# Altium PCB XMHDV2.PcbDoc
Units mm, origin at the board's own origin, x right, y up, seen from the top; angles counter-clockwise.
Board outline 47.29 x 47.29 mm, 2 copper layers (Top Layer, Bottom Layer); 11 components, 11 nets, 140 pads, 0 vias.
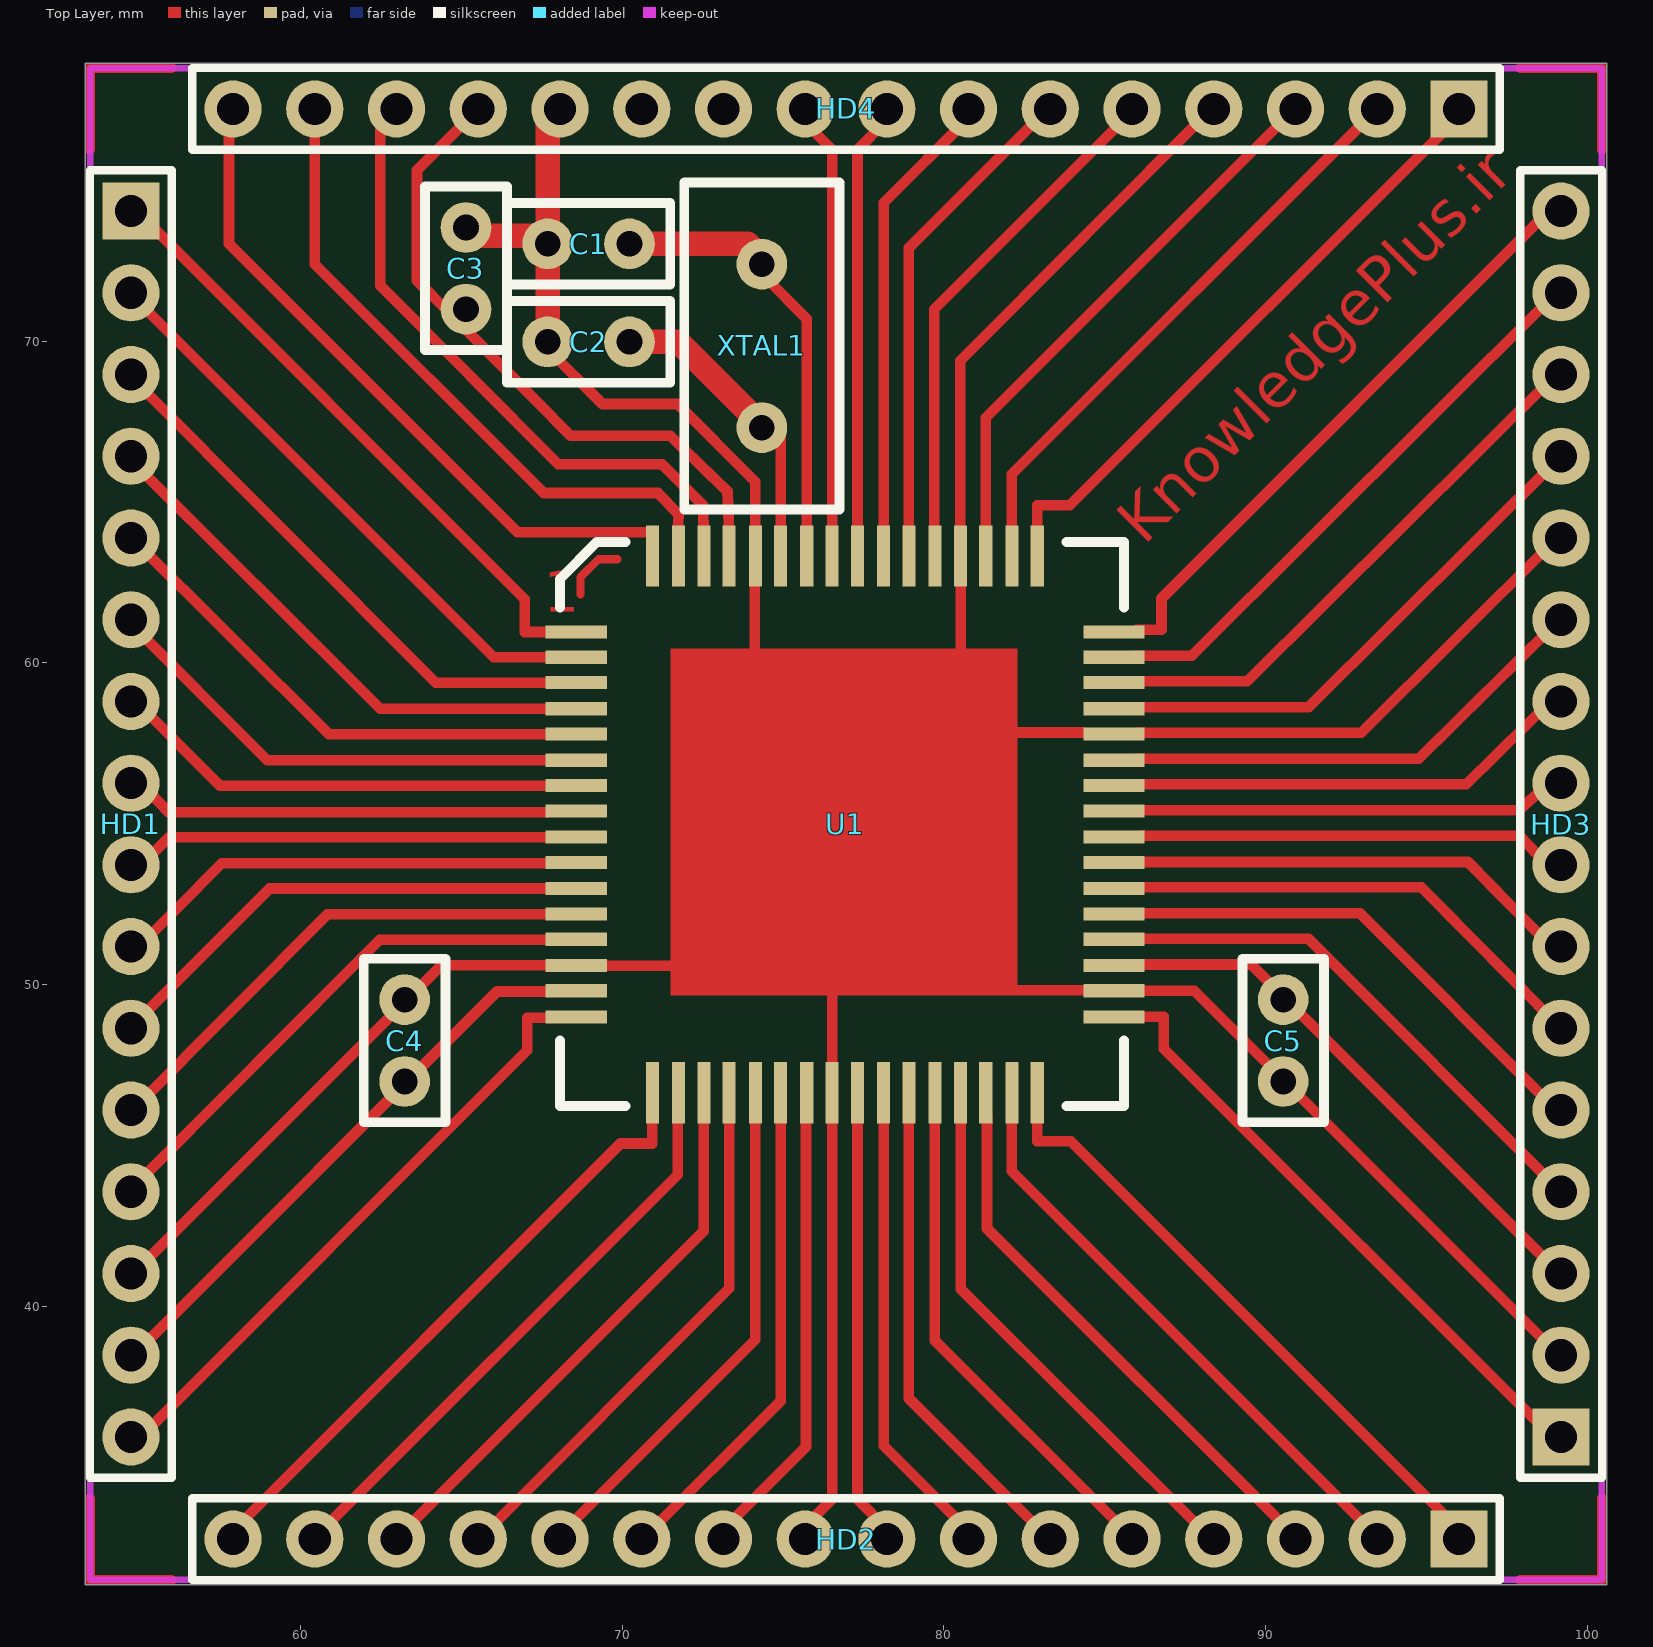
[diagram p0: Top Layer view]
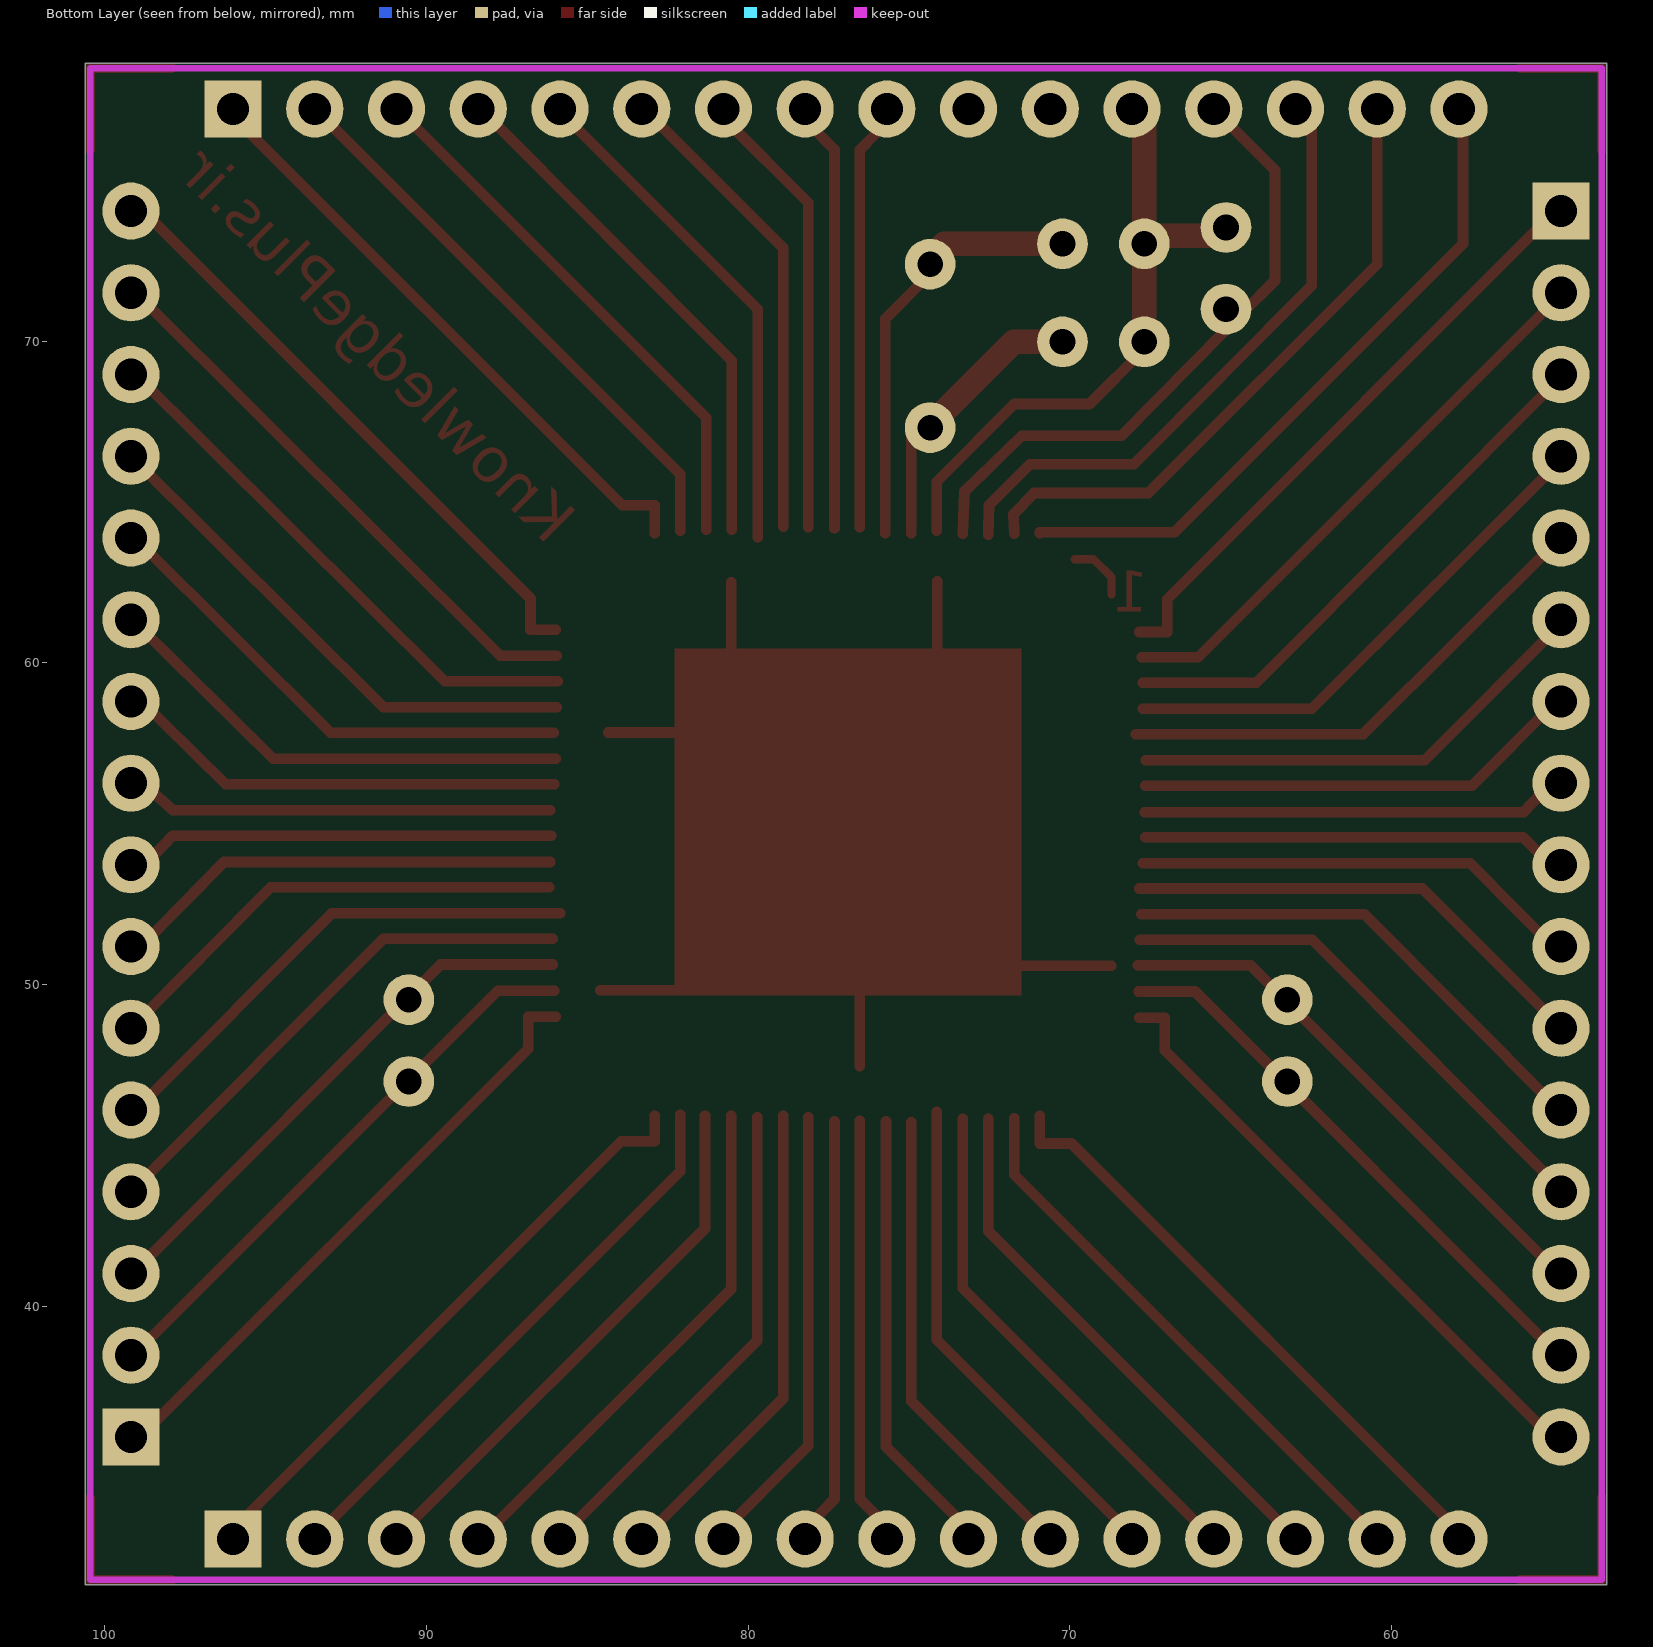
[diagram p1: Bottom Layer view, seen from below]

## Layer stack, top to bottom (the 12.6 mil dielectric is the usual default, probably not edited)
Top Layer: signal copper 0.0356
Dielectric: dielectric 0.32, FR-4, Dk 4.8
Bottom Layer: signal copper 0.0356

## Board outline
53.315,31.344 100.609,31.344 100.609,78.638 53.315,78.638

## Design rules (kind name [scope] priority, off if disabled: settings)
Clearance [All] p1: gap=0.254
PolygonConnect [All] p1: connectstyle=Relief reliefconductorwidth=0.254 reliefentries=4 polygonreliefangle="90 Angle" airgapwidth=0.254
RoutingPriority [All] p1: routingpriority=4
RoutingVias [All] p1: holewidth=0.508 width=1.27 viastyle="Through Hole" minholewidth=0.711 minwidth=1.27 maxholewidth=0.711 maxwidth=1.27
SolderMaskExpansion SolderMaskExpansion_64 [HasPad('U1-64')] p1: expansion=0.051
SolderMaskExpansion SolderMaskExpansion_63 [HasPad('U1-63')] p2: expansion=0.051
SolderMaskExpansion SolderMaskExpansion_62 [HasPad('U1-62')] p3: expansion=0.051
SolderMaskExpansion SolderMaskExpansion_61 [HasPad('U1-61')] p4: expansion=0.051
SolderMaskExpansion SolderMaskExpansion_60 [HasPad('U1-60')] p5: expansion=0.051
SolderMaskExpansion SolderMaskExpansion_59 [HasPad('U1-59')] p6: expansion=0.051
SolderMaskExpansion SolderMaskExpansion_58 [HasPad('U1-58')] p7: expansion=0.051
SolderMaskExpansion SolderMaskExpansion_57 [HasPad('U1-57')] p8: expansion=0.051
SolderMaskExpansion SolderMaskExpansion_56 [HasPad('U1-56')] p9: expansion=0.051
SolderMaskExpansion SolderMaskExpansion_55 [HasPad('U1-55')] p10: expansion=0.051
SolderMaskExpansion SolderMaskExpansion_54 [HasPad('U1-54')] p11: expansion=0.051
SolderMaskExpansion SolderMaskExpansion_53 [HasPad('U1-53')] p12: expansion=0.051
SolderMaskExpansion SolderMaskExpansion_52 [HasPad('U1-52')] p13: expansion=0.051
SolderMaskExpansion SolderMaskExpansion_51 [HasPad('U1-51')] p14: expansion=0.051
SolderMaskExpansion SolderMaskExpansion_50 [HasPad('U1-50')] p15: expansion=0.051
SolderMaskExpansion SolderMaskExpansion_49 [HasPad('U1-49')] p16: expansion=0.051
SolderMaskExpansion SolderMaskExpansion_48 [HasPad('U1-48')] p17: expansion=0.051
SolderMaskExpansion SolderMaskExpansion_47 [HasPad('U1-47')] p18: expansion=0.051
SolderMaskExpansion SolderMaskExpansion_46 [HasPad('U1-46')] p19: expansion=0.051
SolderMaskExpansion SolderMaskExpansion_45 [HasPad('U1-45')] p20: expansion=0.051
SolderMaskExpansion SolderMaskExpansion_44 [HasPad('U1-44')] p21: expansion=0.051
SolderMaskExpansion SolderMaskExpansion_43 [HasPad('U1-43')] p22: expansion=0.051
SolderMaskExpansion SolderMaskExpansion_42 [HasPad('U1-42')] p23: expansion=0.051
SolderMaskExpansion SolderMaskExpansion_41 [HasPad('U1-41')] p24: expansion=0.051
SolderMaskExpansion SolderMaskExpansion_40 [HasPad('U1-40')] p25: expansion=0.051
SolderMaskExpansion SolderMaskExpansion_39 [HasPad('U1-39')] p26: expansion=0.051
SolderMaskExpansion SolderMaskExpansion_38 [HasPad('U1-38')] p27: expansion=0.051
SolderMaskExpansion SolderMaskExpansion_37 [HasPad('U1-37')] p28: expansion=0.051
SolderMaskExpansion SolderMaskExpansion_36 [HasPad('U1-36')] p29: expansion=0.051
SolderMaskExpansion SolderMaskExpansion_35 [HasPad('U1-35')] p30: expansion=0.051
SolderMaskExpansion SolderMaskExpansion_34 [HasPad('U1-34')] p31: expansion=0.051
SolderMaskExpansion SolderMaskExpansion_33 [HasPad('U1-33')] p32: expansion=0.051
SolderMaskExpansion SolderMaskExpansion_32 [HasPad('U1-32')] p33: expansion=0.051
SolderMaskExpansion SolderMaskExpansion_31 [HasPad('U1-31')] p34: expansion=0.051
SolderMaskExpansion SolderMaskExpansion_30 [HasPad('U1-30')] p35: expansion=0.051
SolderMaskExpansion SolderMaskExpansion_29 [HasPad('U1-29')] p36: expansion=0.051
SolderMaskExpansion SolderMaskExpansion_28 [HasPad('U1-28')] p37: expansion=0.051
SolderMaskExpansion SolderMaskExpansion_27 [HasPad('U1-27')] p38: expansion=0.051
SolderMaskExpansion SolderMaskExpansion_26 [HasPad('U1-26')] p39: expansion=0.051
SolderMaskExpansion SolderMaskExpansion_25 [HasPad('U1-25')] p40: expansion=0.051
SolderMaskExpansion SolderMaskExpansion_24 [HasPad('U1-24')] p41: expansion=0.051
SolderMaskExpansion SolderMaskExpansion_23 [HasPad('U1-23')] p42: expansion=0.051
SolderMaskExpansion SolderMaskExpansion_22 [HasPad('U1-22')] p43: expansion=0.051
SolderMaskExpansion SolderMaskExpansion_21 [HasPad('U1-21')] p44: expansion=0.051
SolderMaskExpansion SolderMaskExpansion_20 [HasPad('U1-20')] p45: expansion=0.051
SolderMaskExpansion SolderMaskExpansion_19 [HasPad('U1-19')] p46: expansion=0.051
SolderMaskExpansion SolderMaskExpansion_18 [HasPad('U1-18')] p47: expansion=0.051
SolderMaskExpansion SolderMaskExpansion_17 [HasPad('U1-17')] p48: expansion=0.051
SolderMaskExpansion SolderMaskExpansion_16 [HasPad('U1-16')] p49: expansion=0.051
SolderMaskExpansion SolderMaskExpansion_15 [HasPad('U1-15')] p50: expansion=0.051
SolderMaskExpansion SolderMaskExpansion_14 [HasPad('U1-14')] p51: expansion=0.051
SolderMaskExpansion SolderMaskExpansion_13 [HasPad('U1-13')] p52: expansion=0.051
SolderMaskExpansion SolderMaskExpansion_12 [HasPad('U1-12')] p53: expansion=0.051
SolderMaskExpansion SolderMaskExpansion_11 [HasPad('U1-11')] p54: expansion=0.051
SolderMaskExpansion SolderMaskExpansion_10 [HasPad('U1-10')] p55: expansion=0.051
SolderMaskExpansion SolderMaskExpansion_9 [HasPad('U1-9')] p56: expansion=0.051
SolderMaskExpansion SolderMaskExpansion_8 [HasPad('U1-8')] p57: expansion=0.051
SolderMaskExpansion SolderMaskExpansion_7 [HasPad('U1-7')] p58: expansion=0.051
SolderMaskExpansion SolderMaskExpansion_6 [HasPad('U1-6')] p59: expansion=0.051
SolderMaskExpansion SolderMaskExpansion_5 [HasPad('U1-5')] p60: expansion=0.051
SolderMaskExpansion SolderMaskExpansion_4 [HasPad('U1-4')] p61: expansion=0.051
SolderMaskExpansion SolderMaskExpansion_3 [HasPad('U1-3')] p62: expansion=0.051
SolderMaskExpansion SolderMaskExpansion_2 [HasPad('U1-2')] p63: expansion=0.051
SolderMaskExpansion SolderMaskExpansion_1 [HasPad('U1-1')] p64: expansion=0.051
SolderMaskExpansion [All] p65: expansion=0.102
Width [All] p1: maxlimit=2.54 minlimit=2.54 preferedwidth=0.254
27 further rules are at their usual default settings.

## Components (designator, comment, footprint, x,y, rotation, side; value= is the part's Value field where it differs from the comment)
C1 "18pF" RAD0.1 70.231,73.025 r180 top
C2 "18pF" RAD0.1 70.231,69.977 r180 top
C3 "100nF" RAD0.1 65.151,73.533 r270 top
C4 "100nF" RAD0.1 63.246,49.53 r270 top
C5 "100nF" RAD0.1 90.551,49.53 r270 top
HD1 "1x16 pin header" SIP16#1 54.737,74.041 r270 top
HD2 "1x16 pin header" SIP16#2 96.012,32.766 r180 top
HD3 "1x16 pin header" SIP16#3 99.187,35.941 r90 top
HD4 "1x16 pin header" SIP16#4 96.012,77.216 r180 top
U1 "ATXMEGA64A3U-AU" QFP64-1 68.58,60.96 r0 top
XTAL1 "16MHz" XTAL1 74.346,72.39 r270 top

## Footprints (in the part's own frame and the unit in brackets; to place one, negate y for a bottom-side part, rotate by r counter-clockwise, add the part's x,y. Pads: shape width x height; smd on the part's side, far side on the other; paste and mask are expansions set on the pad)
QFP64-1 [mil]
  rect 75x16 smd: 1(0,0) 2(0,-31) 3(0,-62) 4(0,-94) 5(0,-125) 6(0,-157) 7(0,-188) 8(0,-219) 9(0,-251) 10(0,-282) 11(0,-314) 12(0,-345) 13(0,-376) 14(0,-408) 15(0,-439) 16(0,-471) 33(658,-471) 34(658,-439) 35(658,-408) 36(658,-376) 37(658,-345) 38(658,-314) 39(658,-282) 40(658,-251) 41(658,-219) 42(658,-188) 43(658,-157) 44(658,-125) 45(658,-94) 46(658,-62) 47(658,-31) 48(658,0)
  rect 16x75 smd: 17(93,-564) 18(125,-564) 19(156,-564) 20(187,-564) 21(219,-564) 22(250,-564) 23(282,-564) 24(313,-564) 25(344,-564) 26(376,-564) 27(407,-564) 28(439,-564) 29(470,-564) 30(501,-564) 31(533,-564) 32(564,-564) 49(564,93) 50(533,93) 51(501,93) 52(470,93) 53(439,93) 54(407,93) 55(376,93) 56(344,93) 57(313,93) 58(282,93) 59(250,93) 60(219,93) 61(187,93) 62(156,93) 63(125,93) 64(93,93)
  silkscreen extent -20,-580 670,110
RAD0.1 [mil]
  round 62 hole 31.5: 0(0,0) 0(100,0)
  silkscreen extent -50,-50 150,50
SIP16#1 [mil]
  rect 70x70 hole 39.37: 1(0,0)
  round 70 hole 39.37: 2(100,0) 3(200,0) 4(300,0) 5(400,0) 6(500,0) 7(600,0) 8(700,0) 9(800,0) 10(900,0) 11(1000,0) 12(1100,0) 13(1200,0) 14(1300,0) 15(1400,0) 16(1500,0)
  silkscreen extent -50,-50 1550,50
SIP16#2 [mil]
  round 70 hole 39.37: 17(1500,0) 18(1400,0) 19(1300,0) 20(1200,0) 21(1100,0) 22(1000,0) 23(900,0) 24(800,0) 25(700,0) 26(600,0) 27(500,0) 28(400,0) 29(300,0) 30(200,0) 31(100,0)
  rect 70x70 hole 39.37: 32(0,0)
  silkscreen extent -50,-50 1550,50
SIP16#3 [mil]
  rect 70x70 hole 39.37: 33(0,0)
  round 70 hole 39.37: 34(100,0) 35(200,0) 36(300,0) 37(400,0) 38(500,0) 39(600,0) 40(700,0) 41(800,0) 42(900,0) 43(1000,0) 44(1100,0) 45(1200,0) 46(1300,0) 47(1400,0) 48(1500,0)
  silkscreen extent -50,-50 1550,50
SIP16#4 [mil]
  rect 70x70 hole 39.37: 49(0,0)
  round 70 hole 39.37: 50(100,0) 51(200,0) 52(300,0) 53(400,0) 54(500,0) 55(600,0) 56(700,0) 57(800,0) 58(900,0) 59(1000,0) 60(1100,0) 61(1200,0) 62(1300,0) 63(1400,0) 64(1500,0)
  silkscreen extent -50,-50 1550,50
XTAL1 [mil]
  round 62 hole 31.5: 0(0,0) 0(200,0)
  silkscreen extent -100,-95 300,95

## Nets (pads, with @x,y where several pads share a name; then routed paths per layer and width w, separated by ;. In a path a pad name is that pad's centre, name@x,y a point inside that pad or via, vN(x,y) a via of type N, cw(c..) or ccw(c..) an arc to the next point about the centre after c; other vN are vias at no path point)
GND: 
M_A: 
Netbridge_4: 
Nethdr_xmega1_1: 
Nethdr_xmega2_16: 
NetLCD_18: 
SDA: 
TCK: 
TDI: 
TDO: 
TMS: 
pads on no net: C1.0 C2.0 C3.0 C4.0 C5.0 HD1.1 HD1.2 HD1.3 HD1.4 HD1.5 HD1.6 HD1.7 HD1.8 HD1.9 HD1.10 HD1.11 HD1.12 HD1.13 HD1.14 HD1.15 HD1.16 HD2.17 HD2.18 HD2.19 HD2.20 HD2.21 HD2.22 HD2.23 HD2.24 HD2.25 HD2.26 HD2.27 HD2.28 HD2.29 HD2.30 HD2.31 HD2.32 HD3.33 HD3.34 HD3.35 HD3.36 HD3.37 HD3.38 HD3.39 HD3.40 HD3.41 HD3.42 HD3.43 HD3.44 HD3.45 HD3.46 HD3.47 HD3.48 HD4.49 HD4.50 HD4.51 HD4.52 HD4.53 HD4.54 HD4.55 HD4.56 HD4.57 HD4.58 HD4.59 HD4.60 HD4.61 HD4.62 HD4.63 HD4.64 U1.1 U1.2 U1.3 U1.4 U1.5 U1.6 U1.7 U1.8 U1.9 U1.10 U1.11 U1.12 U1.13 U1.14 U1.15 U1.16 U1.17 U1.18 U1.19 U1.20 U1.21 U1.22 U1.23 U1.24 U1.25 U1.26 U1.27 U1.28 U1.29 U1.30 U1.31 U1.32 U1.33 U1.34 U1.35 U1.36 U1.37 U1.38 U1.39 U1.40 U1.41 U1.42 U1.43 U1.44 U1.45 U1.46 U1.47 U1.48 U1.49 U1.50 U1.51 U1.52 U1.53 U1.54 U1.55 U1.56 U1.57 U1.58 U1.59 U1.60 U1.61 U1.62 U1.63 U1.64 XTAL1.0
copper on no net: | length 1063.8
  Top Layer w0.254: 68.707,62.128 68.707,62.662 69.266,63.221 69.863,63.221
  Top Layer w0.305: 53.467,34.036 53.467,31.496 56.007,31.496 ; 53.467,75.946 53.467,78.486 56.007,78.486 ; 97.917,31.496 100.457,31.496 100.457,34.036 ; 97.917,78.486 100.457,78.486 100.457,75.946
  Top Layer w0.33: 54.661,43.561 62.474,51.398 67.824,51.398 ; 54.661,61.29 58.979,56.972 67.64,56.972 ; 54.661,66.37 62.484,58.572 67.742,58.572 ; 54.686,40.894 64.389,50.597 67.894,50.597 ; 54.686,68.936 64.212,59.386 67.737,59.386 ; 54.712,50.902 57.561,53.773 67.736,53.773 ; 54.712,71.476 66.015,60.173 67.767,60.173 ; 54.712,74.244 66.98,61.976 66.98,60.96 67.843,60.96 ; 54.788,48.717 59.055,52.984 67.843,52.984 ; 54.839,63.805 60.887,57.786 67.962,57.786 ; 54.915,35.814 67.056,47.955 67.056,48.971 67.843,48.971 ; 54.915,38.583 66.116,49.784 67.869,49.784 ; 54.915,46.228 60.846,52.184 67.78,52.184 ; 54.915,58.776 57.506,56.185 67.666,56.185 ; 54.991,53.67 55.931,54.585 67.666,54.585 ; 55.093,56.21 55.899,55.361 67.674,55.361 ; 57.683,32.791 69.952,45.06 70.942,45.06 70.942,45.923 ; 57.76,76.962 57.785,76.708 57.785,73.025 66.751,64.059 70.942,64.059 70.942,64.033 ; 60.427,32.791 71.73,44.094 71.73,45.847 ; 60.452,77.216 60.452,72.39 67.564,65.278 71.12,65.278 71.755,64.618 71.73,64.008 ; 62.484,77.572 62.484,71.73 68.021,66.167 71.247,66.167 72.517,64.897 72.542,63.983 ; 62.967,32.766 72.542,42.342 72.542,45.822 ; 64.643,70.866 63.627,71.882 63.627,75.311 65.913,77.597 ; 65.151,70.358 68.402,67.056 71.501,67.056 73.279,65.329 73.33,64.008 ; 65.532,32.741 73.33,40.564 73.33,45.822 ; 67.691,69.748 69.393,68.047 71.73,68.047 74.143,65.634 74.143,64.11 ; 68.097,32.918 74.143,38.964 74.143,46.05 ; 68.72,50.584 71.933,50.584 ; 70.612,32.741 74.93,37.059 74.93,45.72 ; 73.127,33.045 75.717,35.636 75.717,45.745 ; 74.13,60.249 74.13,62.535 ; 74.498,71.933 75.743,70.688 75.743,64.033 ; 74.93,64.033 74.93,66.98 ; 75.616,76.886 76.53,75.946 76.53,64.211 ; 75.692,33.172 76.53,34.011 76.53,45.771 ; 76.53,47.46 76.53,50.279 ; 77.318,45.745 77.318,34.011 78.232,33.071 ; 77.318,64.186 77.318,75.946 78.156,76.784 ; 78.13,45.872 78.13,35.662 81.001,32.791 ; 78.13,64.211 78.13,74.295 80.721,76.886 ; 78.918,45.923 78.918,37.135 83.185,32.868 ; 78.918,64.237 78.918,72.898 83.236,77.216 ; 79.705,63.906 79.705,70.993 85.75,77.038 ; 79.718,45.872 79.718,38.938 85.674,32.995 ; 80.518,64.135 80.518,69.393 88.316,77.216 ; 80.531,45.923 80.531,40.538 88.341,32.741 ; 80.531,60.249 80.531,62.509 ; 81.305,64.135 81.305,67.615 90.881,77.191 ; 81.343,45.923 81.343,42.418 91.008,32.766 ; 82.067,49.822 84.595,49.822 ; 82.08,57.836 84.353,57.836 ; 82.118,45.949 82.118,44.196 93.32,32.995 ; 82.118,64.11 82.118,65.862 93.421,77.165 ; 82.906,45.923 82.906,45.136 83.947,45.136 96.088,32.995 ; 82.906,64.033 82.906,64.897 83.922,64.897 96.19,77.165 ; 85.852,52.222 92.939,52.222 98.984,46.152 ; 85.928,59.423 89.433,59.423 99.136,69.063 ; 85.954,58.623 91.338,58.623 99.162,66.396 ; 85.954,60.223 87.706,60.223 98.908,71.374 ; 85.979,48.997 86.843,48.997 86.843,48.006 99.111,35.738 ; 85.979,57.023 94.767,57.023 99.035,61.239 ; 85.979,61.023 86.766,61.023 86.766,62.001 98.908,74.143 ; 86.03,49.809 87.782,49.809 99.111,38.481 ; 86.03,56.223 96.241,56.223 99.111,59.055 ; 86.042,57.823 92.977,57.823 98.908,63.729 ; 86.081,50.622 89.56,50.622 99.136,41.021 ; 86.081,51.422 91.338,51.422 99.162,43.586 ; 86.131,54.623 97.892,54.623 98.73,53.746 ; 86.157,53.81 96.291,53.81 98.882,51.181 ; 86.157,55.423 97.892,55.423 98.831,56.286 ; 86.182,53.023 94.844,53.023 99.162,48.666
  Top Layer w0.762: 65.151,73.279 67.691,73.279 ; 67.691,69.977 67.691,73.279 ; 68.072,77.089 67.691,76.708 67.691,73.279 ; 70.231,69.977 71.755,69.977 74.422,67.31 ; 70.231,73.025 73.914,73.025 74.422,72.517

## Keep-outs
Keep-Out Layer:
  lines w0.203: 53.467,31.496 100.457,31.496 100.457,78.486 53.467,78.486 53.467,31.496

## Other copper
Top Layer:
  rectangle: 71.501,49.657 82.296,60.452
  text "KnowledgePlus.ir" at 86.233,63.627 h1.4 r45
  text "1" at 67.564,61.595 h1.27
